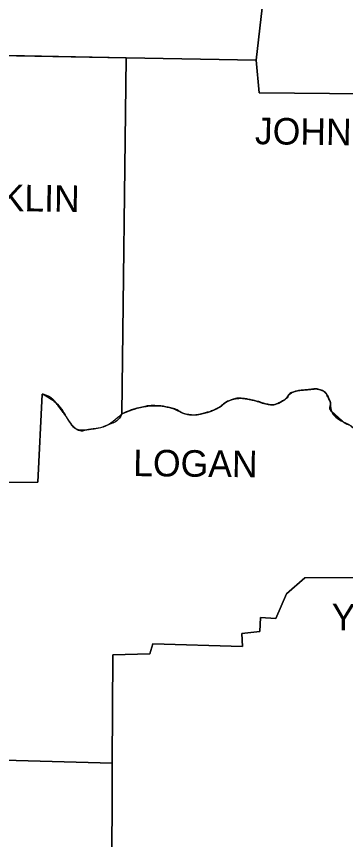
# Model space of a CAD drawing. Extents: x -28335 to 1228743, y -22428 to 152440.
# Drawn here: x 26142 to 27348, y 12147 to 15169 of the extents above; entities that cross this region are included whole.
import ezdxf

# ---------------------------------------------------------------- set-up
doc = ezdxf.new("R2010")
doc.units = 0
doc.layers.add('Level 16', color=7, linetype='Continuous')
doc.layers.add('Level 8', color=7, linetype='Continuous')

msp = doc.modelspace()

# ---------------------------------------------------------------- linework, layer by layer
at = {"layer": 'Level 16'}
for p, q in [((26528.9, 13710.1), (26544.8, 15017.1)), ((26544.8, 15017.1), (26528.9, 13710.1)), ((26544.8, 15017.2), (26544.8, 15017.1)), ((26544.8, 15017.1), (27020.5, 15008.1)), ((27020.5, 15008.1), (26544.8, 15017.1)), ((27020.5, 15008.1), (27031.8, 14888)), ((27031.8, 14888), (27020.5, 15008.1)), ((27031.8, 14888), (28651.4, 14874.9)), ((28088.1, 14879.5), (27031.8, 14888)), ((26968.5, 13767), (26970.6, 13766.7)), ((26760.8, 13709.9), (26769, 13707.9)), ((27296.8, 13719.2), (27334.5, 13684.8)), ((27036.3, 12962.6), (27034.1, 12910.5)), ((27034.1, 12910.5), (26968.4, 12903.7)), ((26642.2, 12865.2), (26630.8, 12828.9)), ((26494.9, 12824.4), (26493.6, 12427.1)), ((26630.8, 12828.9), (26494.9, 12824.4)), ((26493.6, 12427.1), (26490.4, 11499.2))]:
    msp.add_line(p, q, dxfattribs=at)
for points in [[(26046.4, 16641.3), (25862.9, 16115.8), (25826.7, 15275.4), (25799.5, 15273.1), (25786.3, 15026.5), (25785.9, 15019.4), (25919.5, 15008.1), (25939.9, 15028.5), (26544.8, 15017.1)], [(27149.2, 16240.9), (27158.7, 16113.5), (27262.9, 16106.7), (27235.7, 15726.2), (27188.1, 15728.5), (27179, 15667.3), (27124.7, 15667.3), (27122.4, 15563.1), (27088.4, 15560.8), (27077.1, 15427.2), (27027.3, 15420.4), (27020.5, 15216.5), (27043.1, 15200.6), (27020.5, 15008.1)], [(27020.5, 15008.1), (27043.1, 15200.6), (27020.5, 15216.5), (27027.3, 15420.4)], [(26544.8, 15017.1), (26544.8, 15017.1), (25985.2, 15027.6)], [(26544.8, 15017.1), (26544.8, 15017.2)], [(25616.3, 13104.2), (25618.2, 13168.7), (25910.5, 13161.9), (25926.3, 13456.4), (26220.8, 13458.7), (26236.7, 13782.6)], [(26236.7, 13782.6), (26220.8, 13458.7), (25926.3, 13456.4)], [(26493.6, 12427.1), (26494.9, 12824.4), (26630.8, 12828.9), (26642.2, 12865.2), (26970.6, 12856.1), (26968.4, 12903.7), (27034.1, 12910.5), (27036.3, 12962.6), (27093, 12958.1), (27131.5, 13048.7), (27199.4, 13107.6), (27715.9, 13109.8), (27725, 13436)], [(27725, 13436), (27715.9, 13109.8), (27199.4, 13107.6), (27131.5, 13048.7)], [(25616.3, 13104.2), (25609.2, 12865.2), (25303.4, 12862.9), (25294.3, 12559.4), (25486.9, 12548), (25480.1, 12455.2), (26493.6, 12427.1)], [(27131.5, 13048.7), (27093, 12958.1), (27036.3, 12962.6)], [(26968.4, 12903.7), (26970.6, 12856.1), (26642.2, 12865.2)], [(26493.6, 12427.1), (25480.1, 12455.2), (25486.9, 12548), (25294.3, 12559.4), (25299.9, 12745.5)], [(25856.1, 11216.1), (26010.1, 11202.5), (26012.4, 11340.7), (26171, 11345.2), (26168.7, 11381.4), (26275.2, 11381.4), (26277.5, 11431.3), (26386.2, 11429), (26377.1, 11497), (26490.4, 11499.2), (26493.6, 12427.1)]]:
    msp.add_lwpolyline(points, dxfattribs=at)
for points in [[(26236.7, 13782.6), (26286.5, 13750.9), (26325, 13698.8), (26359, 13655.8), (26415.6, 13653.5), (26460.9, 13662.5), (26528.9, 13710.1)], [(26325, 13698.8), (26315.4, 13711.8), (26306, 13724.9), (26296.4, 13737.9), (26286.5, 13750.9)], [(26359, 13655.8), (26348.8, 13666), (26340.4, 13676.8), (26332.8, 13687.8), (26325, 13698.8)]]:
    msp.add_spline(points, degree=3, dxfattribs=at)
for points, degree in [([(26286.5, 13750.9), (26274.1, 13766.6), (26255, 13776.8), (26236.7, 13782.6)], 2), ([(27725, 13436), (27711.2, 13450.2), (27696.4, 13463.3), (27681.9, 13476.8), (27667.4, 13490.3), (27655.5, 13508.1), (27636.6, 13515.3), (27620.4, 13521.5), (27603.5, 13523.1), (27586.8, 13526.6), (27561.1, 13532.1), (27535.5, 13537.5), (27509.8, 13542.5), (27493.4, 13545.7), (27476.5, 13535.4), (27459.9, 13538), (27449.2, 13539.6), (27439.4, 13544.2), (27430.5, 13551.6), (27422.1, 13558.5), (27416.2, 13565.8), (27410.1, 13574.2), (27402.2, 13585.1), (27395.8, 13596.5), (27389.7, 13608.2), (27382.3, 13622.6), (27389.6, 13643.3), (27378.4, 13655.8), (27367.9, 13667.5), (27352, 13671.3), (27339.9, 13680.7), (27324.6, 13692.5), (27309.4, 13704.2), (27296.8, 13719.2), (27287.8, 13729.9), (27296.6, 13747.3), (27290, 13760), (27281.8, 13775.6), (27273, 13793.2), (27256.1, 13798.5), (27240.3, 13803.3), (27224.2, 13800), (27208.5, 13798.5), (27190.3, 13796.7), (27172, 13795.2), (27154.1, 13789.4), (27140.1, 13784.9), (27136.2, 13767), (27122.4, 13760), (27104.4, 13750.8), (27086.2, 13740.8), (27068, 13744.1), (27051.4, 13747.1), (27035, 13753.9), (27018.2, 13757.7), (27002.4, 13761.2), (26986.5, 13764.7), (26970.6, 13766.7), (26954, 13768.8), (26937.4, 13764.6), (26920.8, 13757.7), (26903.1, 13750.3), (26892, 13735.8), (26875.5, 13728.2), (26860.8, 13721.5), (26845.8, 13716.3), (26830.2, 13712.4), (26810.2, 13707.3), (26788.7, 13704.3), (26769, 13707.9), (26749.4, 13711.4), (26732.3, 13725.7), (26712.4, 13730.5), (26694.4, 13734.9), (26676.2, 13738.7), (26658, 13739.6), (26640, 13740.4), (26621.7, 13739.1), (26603.7, 13735), (26577.6, 13729.1), (26553, 13721.4), (26528.9, 13710.1)], 3), ([(27138.3, 13775.7), (27142.7, 13781.6), (27147.2, 13787.1), (27154.1, 13789.4), (27172, 13795.2), (27190.3, 13796.7), (27208.5, 13798.5), (27224.2, 13800), (27240.3, 13803.3), (27256.1, 13798.5)], 3), ([(27256.1, 13798.5), (27273, 13793.2), (27281.8, 13775.6), (27290, 13760)], 2), ([(26875.5, 13728.2), (26892, 13735.8), (26903.1, 13750.3), (26920.8, 13757.7)], 2), ([(26920.8, 13757.7), (26936.7, 13764.3), (26952.6, 13768.5), (26968.5, 13767)], 2), ([(26970.6, 13766.7), (26986.5, 13764.7), (27002.4, 13761.2), (27018.2, 13757.7), (27032.5, 13754.5), (27046.5, 13749.1), (27060.5, 13745.7)], 3), ([(27060.5, 13745.7), (27063, 13745.1), (27065.5, 13744.6), (27068, 13744.1), (27086.2, 13740.8), (27104.4, 13750.8), (27122.4, 13760), (27129.3, 13763.5), (27133.8, 13769.8), (27138.3, 13775.7)], 3), ([(27290, 13760), (27296.6, 13747.3), (27287.8, 13729.9), (27296.8, 13719.2)], 2), ([(26528.9, 13710.1), (26553, 13721.4), (26577.6, 13729.1), (26603.7, 13735), (26621.7, 13739.1), (26640, 13740.4), (26658, 13739.6), (26676.2, 13738.7), (26694.4, 13734.9), (26712.4, 13730.5), (26719.3, 13728.8), (26726, 13726), (26732.5, 13722.8)], 3), ([(26732.5, 13722.8), (26741.9, 13718.2), (26751.2, 13713.1), (26760.8, 13709.9)], 2), ([(26830.2, 13712.4), (26845.8, 13716.3), (26860.8, 13721.5), (26875.5, 13728.2)], 2), ([(26528.9, 13710.1), (26516.8, 13685), (26487.9, 13672.3), (26460.9, 13662.5), (26445.9, 13657.1), (26430.8, 13655.3), (26415.6, 13653.5), (26397, 13651.3), (26374.8, 13642), (26359, 13655.8)], 3), ([(26769, 13707.9), (26772.3, 13707.3), (26775.6, 13706.9), (26778.9, 13706.6)], 2), ([(26778.9, 13706.6), (26795.8, 13705.4), (26813.5, 13708.2), (26830.2, 13712.4)], 2), ([(27334.5, 13684.8), (27336.3, 13683.5), (27338.1, 13682.1), (27339.9, 13680.7)], 2), ([(27339.9, 13680.7), (27344.5, 13677.1), (27349.6, 13674.3), (27354.8, 13671.7)], 2)]:
    msp.add_open_spline(points, degree=degree, dxfattribs=at)
at = {"layer": 'Level 8'}
for points in [[(24157.9, 16213.3), (24589.8, 16210.9), (24601.1, 16360.5), (24757.4, 16360.5), (24771, 16602.8), (25654.5, 16571.1), (25681.7, 16639.1), (26046.4, 16641.3), (25862.9, 16115.8), (25826.7, 15275.4), (25799.5, 15273.1), (25785.9, 15019.4), (25919.5, 15008.1), (25939.9, 15028.5), (27020.5, 15008.1), (27031.8, 14888)], [(27149.2, 16240.9), (27158.7, 16113.5), (27262.9, 16106.7), (27235.7, 15726.2), (27188.1, 15728.5), (27179, 15667.3), (27124.7, 15667.3), (27122.4, 15563.1), (27088.4, 15560.8), (27077.1, 15427.2), (27027.3, 15420.4), (27020.5, 15216.5), (27043.1, 15200.6), (27020.5, 15008.1)], [(27031.8, 14888), (29546.3, 14867.7), (29557.6, 15105.5), (30148, 15098.6)], [(26544.8, 15017.2), (26528.9, 13710.1)], [(26236.7, 13782.6), (26220.8, 13458.7), (25926.3, 13456.4), (25910.5, 13161.9), (25618.2, 13168.7), (25609.2, 12865.2), (25303.4, 12862.9), (25294.3, 12559.4), (25486.9, 12548), (25480.1, 12455.2), (26493.6, 12427.1)], [(27725, 13436), (27715.9, 13109.8), (27199.4, 13107.6), (27131.5, 13048.7), (27093, 12958.1), (27036.3, 12962.6), (27034.1, 12910.5), (26968.4, 12903.7), (26970.6, 12856.1), (26642.2, 12865.2), (26630.8, 12828.9), (26494.9, 12824.4), (26493.6, 12427.1)], [(26493.6, 12427.1), (26490.4, 11499.2), (26377.1, 11497), (26386.2, 11429), (26277.5, 11431.3), (26275.2, 11381.4), (26168.7, 11381.4), (26171, 11345.2), (26012.4, 11340.7), (26010.1, 11202.5), (25856.1, 11216.1), (25831.2, 10101.6), (24959, 10103.8), (24938.7, 9845.6), (24970.4, 9823), (24968.1, 9533), (24314.9, 9561.7)]]:
    msp.add_lwpolyline(points, dxfattribs=at)
for points in [[(26236.7, 13782.6), (26286.5, 13750.9), (26325, 13698.8), (26359, 13655.8), (26415.6, 13653.5), (26460.9, 13662.5), (26528.9, 13710.1)], [(26528.9, 13710.1), (26603.7, 13735), (26658, 13739.6), (26712.4, 13730.5), (26769, 13707.9), (26830.2, 13712.4), (26875.5, 13728.2), (26920.8, 13757.7), (26970.6, 13766.7), (27018.2, 13757.7), (27068, 13744.1), (27122.4, 13760), (27154.1, 13789.4), (27208.5, 13798.5), (27256.1, 13798.5), (27290, 13760), (27296.8, 13719.2), (27339.9, 13680.7), (27378.4, 13655.8), (27389.7, 13608.2), (27410.1, 13574.2), (27430.5, 13551.6), (27459.9, 13538), (27509.8, 13542.5), (27586.8, 13526.6), (27636.6, 13515.3), (27681.9, 13476.8), (27725, 13436)]]:
    msp.add_spline(points, degree=3, dxfattribs=at)

# ---------------------------------------------------------------- texts
for s, rotation, p in [('JOHNSON', 359.3514, (27015.9, 14700)), ('FRANKLIN', 359.1816, (25729.2, 14459.9)), ('LOGAN', 359.3969, (26569.7, 13481.3)), ('YELL', 359.1987, (27296.8, 12915))]:
    msp.add_text(s, height=97.42, rotation=rotation, dxfattribs=at).set_placement(p)

doc.saveas('drawing.dxf')
